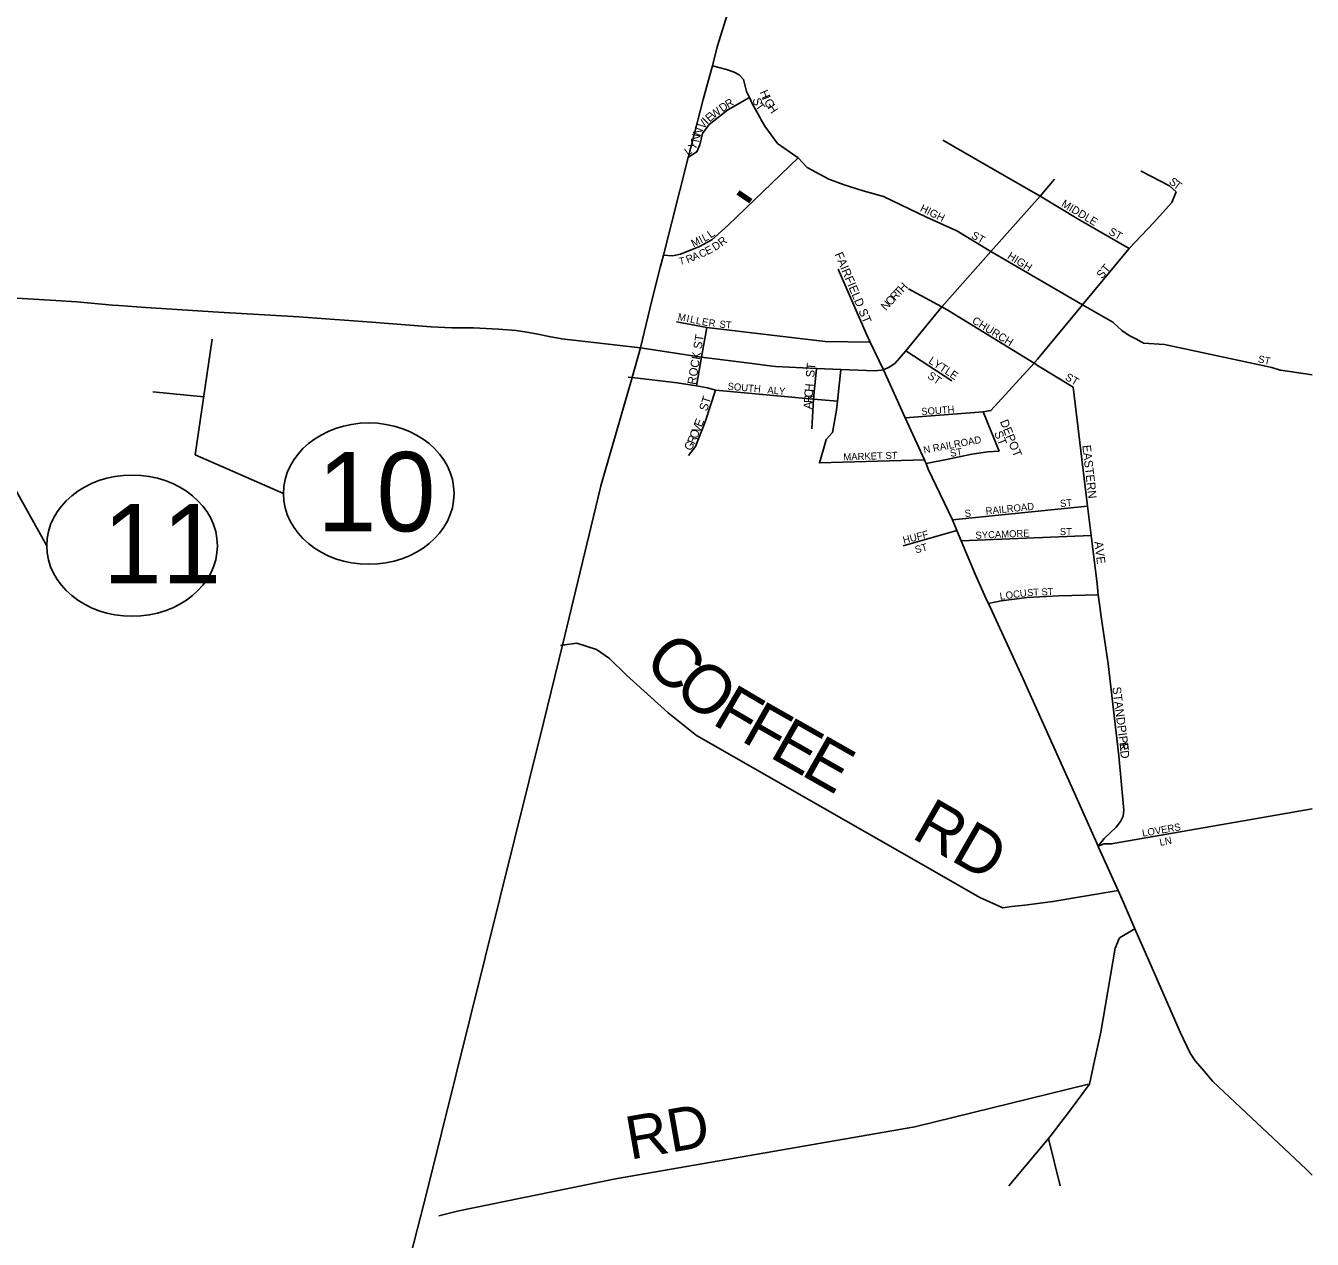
# Model space of a CAD drawing. Extents: x 0 to 784, y 0 to 440.
# Drawn here: x 367.9 to 423, y 48.8 to 100.9 of the extents above; entities that cross this region are included whole.
import ezdxf

# ---------------------------------------------------------------- set-up
doc = ezdxf.new("R2010")
doc.units = 0
doc.layers.add('Default', color=7, linetype='Continuous')

msp = doc.modelspace()

# ---------------------------------------------------------------- linework, layer by layer
at = {"layer": 'Default'}
for p, q in [((375.128, 82.475), (375.864, 87.438)), ((375.496, 84.956), (373.318, 85.178)), ((368.768, 78.575), (366.193, 83.182)), ((378.915, 80.808), (375.128, 82.475))]:
    msp.add_line(p, q, dxfattribs=at)
for points in [[(397.261, 98.958), (397.314, 99.147), (397.513, 99.963), (397.891, 101.156), (398.579, 103.136), (399.073, 104.286), (399.447, 104.946), (401.918, 110.264), (406.439, 120.466), (409.911, 128.097), (411.93, 132.535), (413.444, 135.237), (413.46, 135.264)], [(396.915, 97.71), (396.955, 97.864), (397.261, 98.958)], [(398.742, 98.165), (398.637, 98.564), (398.452, 98.772), (398.239, 98.887), (397.918, 99.003), (397.314, 99.147)], [(395.073, 90.506), (395.207, 91.031), (396.274, 95.219), (396.285, 95.262), (396.915, 97.71)], [(396.572, 95.421), (396.64, 95.467), (396.774, 95.771), (396.879, 96.257), (397.174, 96.645), (397.969, 97.262), (398.898, 97.789)], [(399.359, 96.918), (399.016, 97.54), (398.898, 97.789), (398.77, 98.058), (398.742, 98.165)], [(404.647, 93.545), (403.767, 93.793), (402.96, 94.053), (402.3, 94.3), (401.378, 94.791), (400.988, 95.206), (400.106, 95.819), (399.553, 96.564), (399.402, 96.839), (399.359, 96.918)], [(413.025, 92.566), (411.358, 93.563), (409.822, 94.446), (407.182, 95.964)], [(395.207, 91.031), (395.593, 91.011), (395.946, 91.073), (396.76, 91.401), (397.284, 91.685), (397.991, 92.315), (400.988, 95.206)], [(396.274, 95.219), (396.572, 95.421)], [(417.198, 93.745), (416.909, 94.003), (415.72, 94.625), (415.68, 94.649)], [(404.638, 86.116), (404.915, 86.246), (405.149, 86.407), (405.596, 86.937), (407.149, 88.823), (409.241, 91.192), (411.358, 93.563), (411.98, 94.3)], [(404.647, 93.545), (406.486, 92.666), (407.792, 92.073), (409.241, 91.192)], [(413.236, 88.971), (415.177, 91.314), (416.228, 92.425), (417.013, 93.286), (417.198, 93.745)], [(415.177, 91.314), (413.025, 92.566), (413.025, 92.566)], [(409.241, 91.192), (413.176, 88.899), (414.471, 88.16), (414.864, 87.801), (415.177, 87.592), (415.464, 87.446), (415.686, 87.317), (415.743, 87.289)], [(347.031, 90.494), (347.93, 90.456), (353.656, 90.112), (358.711, 89.794), (366.022, 89.269), (369.161, 89.083), (370.051, 89.029), (371.592, 88.886), (371.856, 88.869)], [(394.229, 87.054), (394.711, 89.085), (395.073, 90.506)], [(404.638, 86.116), (404.066, 87.307), (403.904, 87.677), (402.696, 90.436)], [(407.37, 88.687), (407.149, 88.823), (405.718, 89.589)], [(371.856, 88.869), (373.016, 88.794)], [(411.248, 86.575), (413.176, 88.899), (413.236, 88.971)], [(373.016, 88.794), (376.126, 88.594), (379.569, 88.384), (381.123, 88.271), (381.527, 88.241)], [(411.189, 86.347), (411.102, 86.4), (407.37, 88.687)], [(381.527, 88.241), (382.687, 88.156)], [(382.687, 88.156), (385.249, 87.967), (386.141, 87.923), (387.065, 87.923), (388.143, 87.858), (388.889, 87.804), (389.357, 87.726), (389.75, 87.664), (390.309, 87.544), (390.852, 87.443), (394.229, 87.054)], [(395.764, 88.175), (397.073, 87.931), (402.142, 87.33), (404.066, 87.307)], [(396.621, 85.423), (396.843, 86.655), (397.073, 87.931)], [(415.743, 87.289), (415.797, 87.262), (416.688, 87.196), (421.295, 86.215), (421.657, 86.103), (421.686, 86.099)], [(392.529, 81.138), (393.864, 85.781), (394.229, 87.054)], [(394.229, 87.054), (396.843, 86.655), (398.897, 86.401), (399.776, 86.293)], [(407.57, 85.638), (405.596, 86.937)], [(399.776, 86.293), (400.018, 86.264), (401.77, 86.169), (402.816, 86.136), (404.286, 86.076), (404.638, 86.116)], [(401.661, 85.021), (401.77, 86.169)], [(406.404, 82.256), (401.898, 82.124), (402.077, 82.707), (402.181, 83.132), (402.461, 83.435), (402.627, 84.382), (402.673, 84.771), (402.816, 86.136)], [(406.42, 82.215), (406.404, 82.256), (405.58, 84.051), (404.638, 86.116)], [(409.072, 84.337), (409.247, 84.369), (411.102, 86.4), (411.135, 86.439), (411.248, 86.575)], [(412.774, 85.366), (411.207, 86.336), (411.189, 86.347)], [(421.686, 86.099), (423.029, 85.903)], [(393.701, 85.8), (393.864, 85.781), (395.794, 85.56), (395.797, 85.559)], [(395.797, 85.559), (396.621, 85.423), (397.095, 85.344), (397.436, 85.244), (401.649, 84.864), (402.673, 84.771)], [(396.282, 82.448), (396.579, 82.821), (396.996, 83.887), (397.436, 85.244)], [(401.567, 83.584), (401.649, 84.864), (401.655, 84.96), (401.661, 85.021)], [(413.573, 78.779), (413.544, 79.006), (413.389, 80.271), (412.774, 85.366)], [(405.58, 84.051), (408.92, 84.309), (409.072, 84.337)], [(409.599, 82.635), (408.92, 84.309)], [(409.095, 76.195), (408.576, 77.353), (407.978, 78.786), (407.793, 79.22), (407.602, 79.69), (406.563, 81.854), (406.467, 82.092), (406.42, 82.215)], [(406.467, 82.092), (407.418, 82.286), (408.432, 82.502), (409.111, 82.602), (409.599, 82.635)], [(390.071, 70.977), (390.874, 74.305), (392.493, 81.011), (392.529, 81.138)], [(407.602, 79.69), (413.389, 80.271)], [(405.494, 78.567), (407.793, 79.22)], [(407.978, 78.786), (413.544, 79.006)], [(413.855, 76.473), (413.799, 76.945), (413.573, 78.779)], [(410.617, 72.899), (409.143, 76.088), (409.095, 76.195)], [(409.143, 76.088), (409.691, 76.207), (410.807, 76.347), (412.169, 76.422), (413.855, 76.473)], [(413.938, 75.86), (413.855, 76.473)], [(413.842, 65.693), (414.101, 66.014), (414.618, 66.498), (414.809, 66.751), (414.92, 66.981), (414.946, 67.225), (414.741, 69.555), (414.272, 73.514), (413.97, 75.623), (413.938, 75.86)], [(405.858, 65.152), (396.626, 70.432), (395.413, 71.411), (393.631, 73.026), (392.901, 73.735), (392.345, 74.115), (391.494, 74.387), (390.874, 74.305), (390.798, 74.294)], [(412.772, 68.086), (410.677, 72.767), (410.617, 72.899)], [(385.064, 50.848), (390.071, 70.977)], [(414.932, 63.274), (414.706, 63.791), (413.863, 65.646), (413.842, 65.693), (412.772, 68.086)], [(419.416, 66.659), (423.029, 67.289)], [(413.842, 65.693), (414.101, 65.781), (414.408, 65.786), (419.416, 66.659)], [(414.706, 63.791), (411.908, 63.308), (410.701, 63.156), (410.127, 63.099), (409.759, 63.04), (408.777, 63.483), (405.858, 65.152)], [(418.318, 56.122), (418.015, 56.481), (417.799, 56.816), (417.367, 57.714), (416.025, 60.78), (415.424, 62.149), (414.932, 63.274)], [(413.713, 56.546), (413.968, 57.711), (414.572, 61.309), (414.76, 61.752), (415.424, 62.149)], [(412.657, 54.383), (413.479, 55.479), (413.713, 56.546)], [(423.029, 51.581), (422.767, 51.832), (418.765, 55.592), (418.318, 56.122)], [(385.574, 49.836), (386.443, 50.054), (393.155, 51.415), (405.985, 53.647), (413.379, 55.468), (413.479, 55.479)], [(410.021, 51.125), (410.247, 51.386), (411.723, 53.154), (411.834, 53.287), (412.657, 54.383)], [(412.215, 51.125), (411.723, 53.154)], [(377.579, 21.914), (378.324, 24.635), (378.441, 25.061), (385.064, 50.848)]]:
    msp.add_lwpolyline(points, dxfattribs=at)
for centre in [(382.574, 80.808), (372.426, 78.575)]:
    msp.add_ellipse(centre, major_axis=(3.658, 0), ratio=0.82844, dxfattribs=at)

# ---------------------------------------------------------------- texts
for s, height, rotation, p in [('R', 0.336, 30.9629, (397.98, 97.329)), ('S', 0.366, 283.6615, (399.026, 97.732)), ('H', 0.365, 292.2689, (399.329, 98.03)), ('I', 0.365, 292.2689, (399.433, 97.778)), ('G', 0.363, 300.8564, (399.504, 97.611)), ('E', 0.348, 39.6017, (397.184, 96.725)), ('W', 0.344, 36.8032, (397.363, 96.873)), ('D', 0.343, 35.7978, (397.744, 97.159)), ('T', 0.361, 305.397, (399.124, 97.42)), ('H', 0.362, 303.6212, (399.655, 97.359)), ('V', 0.36, 52.9754, (396.925, 96.411)), ('I', 0.354, 45.2189, (397.088, 96.628)), ('N', 0.366, 78.4303, (396.739, 95.852)), ('N', 0.365, 68.3214, (396.789, 96.104)), ('L', 0.343, 36.0734, (396.263, 95.284)), ('Y', 0.362, 56.8747, (396.543, 95.516)), ('S', 0.346, 321.9652, (416.854, 94.13)), ('-', 2.044, 325.7409, (397.861, 93.142)), ('T', 0.344, 323.1505, (417.047, 93.979)), ('MIDDLE', 0.3363, 328.9291, (412.241, 93.151)), ('HIGH', 0.3294, 333.5668, (406.184, 92.94)), ('ST', 0.3345, 330.1578, (414.268, 91.951)), ('M', 0.33, 26.5969, (396.495, 91.367)), ('I', 0.33, 26.619, (396.826, 91.533)), ('L', 0.33, 26.5997, (396.963, 91.602)), ('L', 0.343, 35.6656, (397.238, 91.745)), ('D', 0.337, 31.7757, (397.421, 91.209)), ('R', 0.346, 37.8887, (397.713, 91.392)), ('ST', 0.3345, 330.1578, (408.377, 91.791)), ('R', 0.322, 21.6529, (396.248, 90.686)), ('A', 0.322, 21.7981, (396.51, 90.79)), ('C', 0.325, 23.8433, (396.815, 90.912)), ('E', 0.33, 27.1466, (397.092, 91.036)), ('FAIRFIELD ST', 0.365, 292.837, (402.542, 91.072)), ('HIGH', 0.3374, 328.1461, (409.924, 90.91)), ('T', 0.307, 9.4257, (395.901, 90.618)), ('ST', 0.3578, 50.1199, (414.017, 89.991)), ('R', 0.355, 46.6419, (405.145, 89.054)), ('T', 0.355, 46.6511, (405.324, 89.243)), ('H', 0.355, 47.0155, (405.484, 89.412)), ('N', 0.355, 46.6487, (404.749, 88.634)), ('O', 0.355, 46.6172, (404.947, 88.844)), ('M', 0.309, 348.5971, (395.802, 88.252)), ('I', 0.309, 348.6107, (396.177, 88.176)), ('L', 0.309, 348.6007, (396.334, 88.145)), ('L', 0.309, 348.6007, (396.584, 88.094)), ('E', 0.309, 348.7428, (396.835, 88.044)), ('R', 0.304, 354.8703, (397.135, 87.987)), ('CHURCH', 0.3371, 328.3271, (408.411, 88.137)), ('ST', 0.3047, 354.092, (397.596, 87.933)), ('ROCK ST', 0.3658, 80.5459, (396.591, 85.46)), ('LYTLE', 0.3395, 326.6598, (406.545, 86.429)), ('ST', 0.3094, 348.2935, (420.685, 86.439)), ('ST', 0.3658, 85.4027, (401.677, 85.777)), ('SOUTH', 0.3043, 354.8575, (397.949, 85.267)), ('H', 0.366, 84.4853, (401.627, 85.159)), ('ST', 0.3412, 325.3869, (406.501, 85.79)), ('ST', 0.3344, 330.1682, (412.401, 85.711)), ('ST', 0.3656, 72.1497, (397.076, 84.321)), ('ALY', 0.3042, 355.098, (399.655, 85.107)), ('R', 0.366, 86.8049, (401.595, 84.682)), ('C', 0.366, 85.6619, (401.609, 84.921)), ('A', 0.366, 86.808, (401.58, 84.416)), ('SOUTH', 0.3039, 4.118, (406.274, 84.173)), ('E', 0.365, 68.5512, (396.846, 83.637)), ('DEPOT', 0.3651, 291.918, (409.629, 83.898)), ('R', 0.365, 66.9003, (396.547, 82.895)), ('O', 0.365, 68.5746, (396.647, 83.129)), ('V', 0.365, 68.5611, (396.747, 83.383)), ('ST', 0.3651, 291.9231, (409.381, 83.412)), ('G', 0.36, 53.8923, (396.346, 82.606)), ('N RAILROAD', 0.3083, 10.6071, (406.384, 82.521)), ('ST', 0.3068, 8.8342, (407.524, 82.382)), ('EASTERN', 0.3658, 276.5586, (413.168, 82.872)), ('MARKET ST', 0.3032, 1.8239, (402.93, 82.227)), ('ST', 0.3047, 5.9094, (412.227, 80.226)), ('S', 0.305, 5.9094, (408.139, 79.799)), ('RAILROAD', 0.3047, 5.8411, (409.041, 79.906)), ('HUFF', 0.3127, 14.5911, (405.52, 78.651)), ('SYCAMORE', 0.3033, 2.4629, (408.594, 78.866)), ('ST', 0.3031, 0, (412.203, 79.027)), ('ST', 0.3137, 15.4373, (406.039, 78.239)), ('AVE', 0.3658, 277.123, (413.683, 78.739)), ('U', 0.306, 7.5102, (410.507, 76.367)), ('S', 0.304, 3.3994, (410.816, 76.408)), ('T', 0.303, 2.6955, (411.072, 76.423)), ('S', 0.303, 2.4999, (411.425, 76.439)), ('T', 0.303, 2.5105, (411.682, 76.451)), ('L', 0.306, 7.6136, (409.649, 76.252)), ('O', 0.306, 7.6236, (409.903, 76.286)), ('C', 0.306, 7.6178, (410.221, 76.329)), ('C', 2.105, 317.4626, (394.283, 73.489)), ('O', 2.088, 320.0353, (395.566, 72.315)), ('F', 2.012, 329.5824, (397.242, 70.953)), ('STANDPIPE', 0.3658, 277.3362, (414.456, 72.498)), ('F', 2.004, 330.4189, (398.482, 70.226)), ('E', 2.004, 330.4557, (399.704, 69.532)), ('E', 2.004, 330.4529, (401.059, 68.764)), ('RD', 0.3658, 277.237, (414.746, 70.125)), ('RD', 2.0074, 330.0786, (405.791, 66.075)), ('LOVERS', 0.3076, 9.7546, (415.763, 66.091)), ('LN', 0.3082, 10.4345, (416.508, 65.698)), ('RD', 1.8465, 9.9785, (393.777, 52.236))]:
    msp.add_text(s, height=height, rotation=rotation, dxfattribs=at).set_placement(p)
for s, p in [('10', (380.372, 79.188)), ('11', (371.176, 76.954))]:
    msp.add_text(s, height=3.4063, dxfattribs=at).set_placement(p)

doc.saveas('drawing.dxf')
